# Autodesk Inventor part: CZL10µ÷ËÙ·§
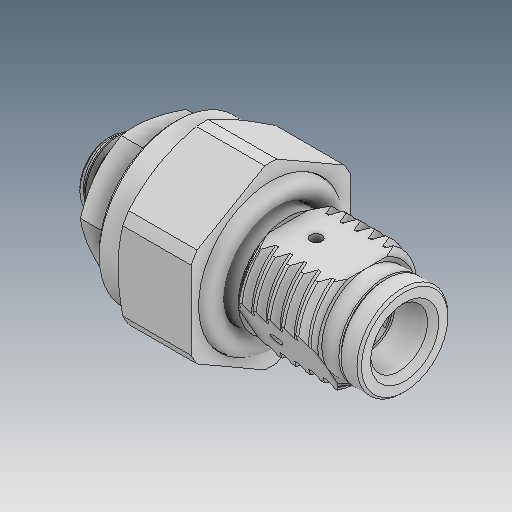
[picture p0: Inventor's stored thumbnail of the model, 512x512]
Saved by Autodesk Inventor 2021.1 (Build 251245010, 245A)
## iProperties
Created: 2019-12
Part Number: CZL10µ÷ËÙ·§
Material: Ogólny
Document SubType Name: Modeling
Designer: user
Density: 1 g/cm^3
Appearance: Domyślna
Author: user
Revision Number: ÈÎºÎ
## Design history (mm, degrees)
feature "ÊäÈë1"
feature "ÊäÈë2"
feature "ÊäÈë3"
feature "ÊäÈë4"
feature "ÊäÈë5"
node "Bryła1"
node "Bryła2"
node "Bryła3"
node "Bryła4"
node "Bryła5"
